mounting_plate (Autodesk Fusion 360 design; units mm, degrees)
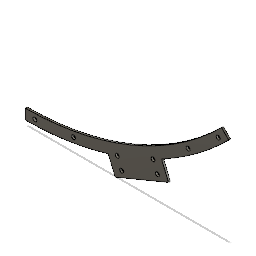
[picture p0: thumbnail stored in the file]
sketch "Sketch1" plane through (0, 0, 0) normal (0, 0, 1) x axis (1, 0, 0)
  line L1 (-0.1099, -297.6938) -> (-0.1099, -286.8938)
  line L2 (210.579, -210.4236) -> (202.9422, -202.7869)
  line L3 (202.9422, -202.7869) -> (-0.1099, -286.8938)
  line L4 (210.579, -210.4236) -> (-0.1099, -297.6938)
  line L5 (139.6676, -337.1874) -> (101.4162, -244.8403)
  line L6 (148.2583, -279.5334) -> (92.8255, -302.4944)
  line L7 (145.9622, -273.9901) -> (90.5294, -296.9511)
  line L8 (141.37, -262.9035) -> (85.9372, -285.8645)
  line L9 (141.0589, -262.1526) -> (148.2583, -279.5334)
  line L10 (92.8255, -302.4944) -> (85.6262, -285.1136)
  arc A1 centre (0, 0) radius 286.8938 clockwise from (202.9422, -202.7869) to (-0.1099, -286.8938)
  arc A2 centre (0, 0) radius 292.2938 clockwise from (206.7621, -206.6038) to (-0.1119, -292.2938)
  circle C1 centre (136.7234, -277.8169) radius 2
  circle C2 centre (99.7682, -293.1243) radius 2
  circle C3 centre (132.1312, -266.7304) radius 2
  circle C4 centre (95.176, -282.0377) radius 2
  circle C5 centre (199.5712, -213.558) radius 2
  circle C6 centre (168.3723, -238.9277) radius 2
  circle C7 centre (9.8901, -292.1264) radius 2
  circle C8 centre (49.8901, -288.0046) radius 2
  arc A3 centre (0, 0) radius 297.6938 clockwise from (85.6262, -285.1136) to (-0.1099, -297.6938)
  arc A4 centre (0, 0) radius 297.6938 clockwise from (210.579, -210.4236) to (141.0589, -262.1526)
  circle C9 centre (0, 0) radius 297.6938
  point P1 (0, 0)
  point P2 (0, 0)
  point P8 (101.4162, -244.8403)
  point P16 (145.9622, -273.9901)
  point P18 (141.37, -262.9035)
  point P19 (136.7234, -277.8169)
  point P20 (99.7682, -293.1243)
  point P21 (132.1312, -266.7304)
  point P22 (95.176, -282.0377)
  point P23 (199.5712, -213.558)
  point P24 (168.3723, -238.9277)
  point P25 (9.8901, -292.1264)
  point P26 (49.8901, -288.0046)
  point P27 (141.0589, -262.1526)
  point P13 (92.8255, -302.4944)
  point P14 (148.2583, -279.5334)
  coincident P1 P2
  concentric A1 A3
  vertical L1
  parallel L3 L4
  midpoint L3 P8
  perpendicular L4 L5
  perpendicular L4 L9
  midpoint L5 L6
  coincident P16 L9
  perpendicular L7 L9
  coincident P18 L9
  perpendicular L8 L9
  coincident L7 P19
  coincident L7 P20
  coincident L8 P21
  coincident L8 P22
  coincident A2 P23
  coincident A2 P24
  coincident A2 P25
  coincident A2 P26
  coincident P27 A3
  concentric A3 A4
  concentric A3 C9
  coincident P27 C9
  dimension "d3" angle L1 L2 = 45
  dimension "d4" = 5.4
  dimension "d5" distance P13 P14 = 60
  dimension "d6" distance L4 L6 = 40
  dimension "d7" distance L6 L7 = 6
  dimension "d8" distance L6 L8 = 18
  dimension "d9" diameter C1 = 4
  dimension "d10" diameter C2 = 4
  dimension "d11" diameter C3 = 4
  dimension "d12" diameter C4 = 4
  dimension "d13" distance P21 L9 = 10
  dimension "d16" distance P19 L9 = 10
  dimension "d17" diameter C5 = 4
  dimension "d18" diameter C6 = 4
  dimension "d19" diameter C7 = 4
  dimension "d20" diameter C8 = 4
  dimension "d21" distance L1 P25 = 10
  dimension "d22" distance L1 P26 = 50
  dimension "d23" distance L2 P23 = 10
  dimension "d24" distance L2 P24 = 50
  dimension "d27" distance A1 A4 = 10.8
extrude "Extrude1" new body sketch "Sketch1" profile of A4 A1 L1 L2 L10 L6 L9 C1 C2 C3 C4 C5 C6 C7 C8 along normal blind 2
sketch "Sketch2" plane through (0, 0, 2) normal (0, 0, 1) x axis (1, 0, 0)
  line L1 (-0.1099, -297.6938) -> (-0.1099, -286.8938)
  line L2 (92.8255, -302.4944) -> (85.6262, -285.1136)
  line L3 (148.2583, -279.5334) -> (92.8255, -302.4944)
  line L4 (141.0589, -262.1526) -> (148.2583, -279.5334)
  line L5 (202.9422, -202.7869) -> (210.579, -210.4236)
  line L6 (141.0589, -262.1526) -> (85.6262, -285.1136)
  circle C1 centre (168.3723, -238.9277) radius 2
  circle C2 centre (9.8901, -292.1264) radius 2
  circle C3 centre (49.8901, -288.0046) radius 2
  circle C4 centre (132.1312, -266.7304) radius 2
  circle C5 centre (95.176, -282.0377) radius 2
  circle C6 centre (199.5712, -213.558) radius 2
  circle C7 centre (99.7682, -293.1243) radius 2
  circle C8 centre (136.7234, -277.8169) radius 2
  arc A1 centre (0, 0) radius 297.6938 clockwise from (85.6262, -285.1136) to (-0.1099, -297.6938)
  arc A2 centre (0, 0) radius 297.6938 clockwise from (210.579, -210.4236) to (141.0589, -262.1526)
  arc A3 centre (0, 0) radius 286.8938 clockwise from (202.9422, -202.7869) to (-0.1099, -286.8938)
  point P12 (85.6262, -285.1136)
  point P19 (85.6262, -285.1136)
  point P16 (141.0589, -262.1526)
  point P20 (141.0589, -262.1526)
  coincident P12 P19
  coincident P16 P20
